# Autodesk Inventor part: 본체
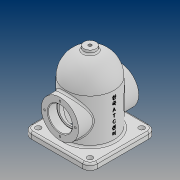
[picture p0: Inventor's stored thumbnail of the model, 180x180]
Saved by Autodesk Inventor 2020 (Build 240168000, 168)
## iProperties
Created: 2021-08
Part Number: 본체
Material: 일반
Document SubType Name: Modeling
Designer: PC312-
Density: 1 g/cm^3
Appearance: 기본값
Author: PC312-
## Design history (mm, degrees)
sketch "스케치1"
  geometry: C1 r 40 at (0, 0); 1 further point
  constraints: 1 centre point, 1 coincident
  dimensions: "d0" = 80 diameter of C1
extrude "돌출1" new body sketch "스케치1" distance "d1" = 36; taper "d3" = 0 deg; dims "d2" = 48, "d4" = 0
node "작업 평면1"
sketch "스케치4"
  geometry: C1 r 40 at (0, 0) reference; 1 further point
extrude "돌출4" join sketch "스케치4" distance "d15" = 40; taper "d16" = 0 deg
fillet "모깎기2" dims "d17" = 40
feature "쉘2" dims "d25" = 8
sketch "스케치7"
  geometry: C1 r 31 at (0, 0); 1 further point
  constraints: 1 centre point, 1 coincident
  dimensions: "d26" = 62 diameter of C1
extrude "돌출5" join sketch "스케치7" stored distance "d27" = 40; taper "d28" = 0 deg
sketch "스케치8"
  geometry: C1 r 31 at (0, 0) reference; 2 further points
  constraints: 1 coincident
hole "구멍2" sketch "스케치8" at (0, 0) diameter "d29" = 33; stored, may be unused: countersink angle "d33" = 90 deg, drill point angle "d35" = 0 deg; dims "d30" = 6, "d31" = 40, "d32" = 15, "d34" = 40
sketch "스케치9"
  geometry: L1 (-55, -55)-(55, -55); L2 (55, -55)-(55, 55); L3 (55, 55)-(-55, 55); L4 (-55, 55)-(-55, -55); L5 (-55, -55)-(55, 55); L6 (55, -55)-(-55, 55); C1 r 40 at (0, 0) reference; 1 further point
  constraints: 12 end point, 2 midpoint, 2 parallel, 1 horizontal, 1 perpendicular
  dimensions: "d36" = 110 distance of L3.end L2.end; "d37" = 110 distance of L2.end L1.end
extrude "돌출6" join sketch "스케치9" distance "d38" = 10; taper "d39" = 0 deg
node "작업 평면2"
sketch "스케치10"
  geometry: C1 r 10 at (0, 0); 1 further point
  constraints: 1 centre point, 1 coincident
  dimensions: "d41" = 20 diameter of C1
extrude "돌출7" join sketch "스케치10" stored distance "d42" = 10; taper "d43" = 0 deg
sketch "스케치11"
  geometry: C1 r 10 at (0, 0) reference; 2 further points
  constraints: 1 coincident
hole "구멍3" sketch "스케치11" at (0, 0) diameter "d44" = 5.1881; stored, may be unused: countersink angle "d48" = 90 deg, drill point angle "d50" = 0 deg; dims "d45" = 20, "d46" = 40, "d47" = 15, "d49" = 20
sketch "스케치12"
  geometry: 2 further points
  constraints: 1 vertical alignment
  dimensions: "d51" = 25.5 distance of point (0, 0) point (0, 25.5)
hole "구멍4" sketch "스케치12" at (0, 25.5) diameter "d52" = 3.242; stored, may be unused: countersink angle "d56" = 90 deg, drill point angle "d58" = 118 deg; dims "d53" = 8, "d54" = 40, "d55" = 15, "d57" = 10
fillet "모깎기3" dims "d62" = 12
fillet "모깎기4" dims "d63" = 0.3
fillet "모깎기5" dims "d64" = 3
fillet "모깎기6" dims "d65" = 3
chamfer "모따기1" distance "d66" = 1; stored, may be unused: second distance "d67" = 2, angle "d68" = 45 deg
chamfer "모따기2" distance "d69" = 1; stored, may be unused: second distance "d70" = 2, angle "d71" = 45 deg
node "작업 평면3"
sketch "스케치13"
  geometry: L1 (-48, -43)-(-48, 43) reference; 2 further points
  constraints: 1 coincident, 1 other
  dimensions: "d73" = 48 distance from line of L1 point (0, 0)
feature "엠보싱1" sketch "스케치13" dims "d74" = 0.5, "d75" = 0
sketch "스케치14"
  geometry: A1 r 12 centre (-43, -43) between (-55, -43) and (-43, -55) reference; A2 r 12 centre (-43, 43) between (-43, 55) and (-55, 43) reference; A3 r 12 centre (43, 43) between (55, 43) and (43, 55) reference; A4 r 12 centre (43, -43) between (43, -55) and (55, -43) reference; 5 further points
  constraints: 4 coincident
hole "구멍5" sketch "스케치14" at (43, -43), (-43, 43), (-43, -43), (43, 43) diameter "d76" = 9; stored, may be unused: countersink angle "d80" = 90 deg, drill point angle "d82" = 0 deg; dims "d77" = 8, "d78" = 40, "d79" = 15, "d81" = 10
node "솔리드1"
mirror "미러1"
pattern_circular "원형 패턴1" dims angle "d60" = 360 deg
mirror "미러2"
feature "A9D066F2-1C7D-4E18-AEED-F7BC21143FA4" dims "d29" = 33, "d30" = 6, "d31" = 40, "d32" = 15, "d33" = 90 deg, "d34" = 40, "d35" = 0
other parameters: "d40" = -129
